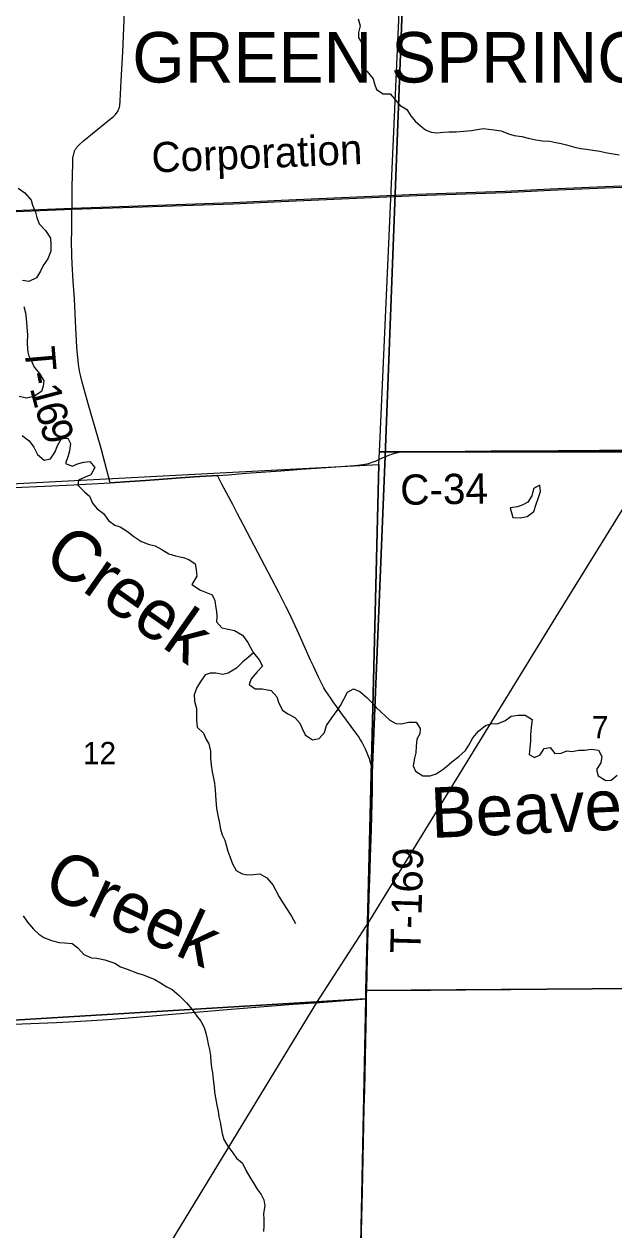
# Model space of a CAD drawing. Extents: x -8.5 to 18.7, y -20.3 to 7.
# Drawn here: x -2.162 to 0.051, y -15.571 to -11.043 of the extents above; entities that cross this region are included whole.
import ezdxf

# ---------------------------------------------------------------- set-up
doc = ezdxf.new("R2010")
doc.units = 0
for name, color, linetype in [('GM_X_Corporation', 7, 'Continuous'), ('GM_X_Corporation_Text', 7, 'Continuous'), ('GM_X_County_Road', 7, 'Continuous'), ('GM_X_County_Road_Text', 7, 'Continuous'), ('GM_X_Minor_Lake', 7, 'Continuous'), ('GM_X_Minor_River', 7, 'Continuous'), ('GM_X_Minor_River_Text', 7, 'Continuous'), ('GM_X_Rail_Line', 7, 'Continuous'), ('GM_X_Rail_Line_Text', 7, 'Continuous'), ('GM_X_Section', 7, 'Continuous'), ('GM_X_Section_Text', 7, 'Continuous'), ('GM_X_Township_Road', 7, 'Continuous'), ('GM_X_Township_Road_Text', 7, 'Continuous')]:
    doc.layers.add(name, color=color, linetype=linetype)

msp = doc.modelspace()

# ---------------------------------------------------------------- linework, layer by layer
at = {"layer": 'GM_X_Corporation'}
for points in [[(-0.7294, -10.6288), (-0.8073, -12.6653), (-0.8563, -13.8563), (-0.8562, -13.8576), (-0.8558, -13.8824), (-0.8563, -13.9234), (-0.8576, -13.9681), (-0.8606, -14.0687), (-0.8638, -14.1703), (-0.8653, -14.2148), (-0.8687, -14.3231), (-0.8738, -14.4921), (-0.8766, -14.6077), (-0.8781, -14.6701), (-0.8783, -14.6907), (-0.8786, -14.7019), (-0.8791, -14.7405), (-0.8831, -14.922), (-0.8855, -15.0451), (-0.8872, -15.1105), (-0.8888, -15.1767), (-0.8939, -15.428), (-0.8959, -15.526), (-0.9022, -15.7882)], [(-0.9022, -15.7882), (-0.8959, -15.526), (-0.8939, -15.428), (-0.8888, -15.1767), (-0.8872, -15.1105), (-0.8855, -15.0451), (-0.8831, -14.922), (-0.8791, -14.7405), (-0.8786, -14.7019), (-0.8783, -14.6907), (-0.8781, -14.6701), (-0.8766, -14.6077), (-0.8738, -14.4921), (-0.8687, -14.3231), (-0.8653, -14.2148), (-0.8638, -14.1703), (-0.8606, -14.0687), (-0.8576, -13.9681), (-0.8563, -13.9234), (-0.8558, -13.8824), (-0.8562, -13.8576), (-0.8563, -13.8563), (-0.8073, -12.6653), (-0.7294, -10.6288)]]:
    msp.add_lwpolyline(points, dxfattribs=at)
at = {"layer": 'GM_X_County_Road'}
for points in [[(-1.4372, -12.7375), (-1.3968, -12.7349), (-1.3286, -12.7295), (-1.1997, -12.7202), (-1.1228, -12.7142), (-0.974, -12.7037), (-0.9244, -12.7003), (-0.8997, -12.6979), (-0.8839, -12.6955), (-0.8694, -12.6922), (-0.8565, -12.6883), (-0.8438, -12.6835), (-0.8292, -12.6769), (-0.8068, -12.6664)], [(-0.8068, -12.6664), (-0.7961, -12.6621), (-0.7842, -12.6581), (-0.7707, -12.6535), (-0.7556, -12.6503), (-0.742, -12.6488), (-0.7319, -12.6483), (-0.7151, -12.6481), (-0.6765, -12.6472), (-0.5074, -12.6465), (-0.449, -12.6462), (-0.4092, -12.6457), (-0.3508, -12.6455), (-0.1581, -12.644), (-0.0848, -12.6435), (-0.0039, -12.6428), (0.0856, -12.6428)], [(-2.9024, -12.811), (-2.644, -12.8008), (-2.4067, -12.7911), (-2.198, -12.7824), (-1.9759, -12.7724), (-1.8397, -12.7655)], [(-1.8397, -12.7655), (-1.7654, -12.7603), (-1.7075, -12.7563), (-1.5256, -12.7433), (-1.4372, -12.7375)]]:
    msp.add_lwpolyline(points, dxfattribs=at)
at = {"layer": 'GM_X_Minor_Lake'}
for points in [[(-0.3384, -12.859), (-0.328, -12.8955), (-0.3016, -12.8971), (-0.2743, -12.8912), (-0.25, -12.8724), (-0.2415, -12.8459), (-0.2323, -12.8209), (-0.2246, -12.7975), (-0.2267, -12.7739), (-0.243, -12.783)], [(-0.243, -12.783), (-0.251, -12.7874), (-0.2572, -12.814), (-0.2717, -12.8382), (-0.2907, -12.8479), (-0.3112, -12.8554), (-0.3384, -12.859)]]:
    msp.add_lwpolyline(points, dxfattribs=at)
at = {"layer": 'GM_X_Minor_River'}
for points in [[(-0.9083, -11.0235), (-0.9009, -11.0493), (-0.9071, -11.0736), (-0.9073, -11.0933), (-0.893, -11.1184), (-0.8811, -11.1435), (-0.8866, -11.17), (-0.8936, -11.1988), (-0.8748, -11.2209), (-0.853, -11.2476), (-0.847, -11.2674), (-0.8404, -11.2879), (-0.8155, -11.3047), (-0.7882, -11.3049), (-0.7725, -11.3239), (-0.7522, -11.3468), (-0.7265, -11.3637), (-0.7115, -11.3873), (-0.695, -11.4071), (-0.6754, -11.4247), (-0.6558, -11.44), (-0.6354, -11.4484), (-0.6135, -11.4508), (-0.5885, -11.4487), (-0.5688, -11.4473), (-0.5416, -11.4467), (-0.5135, -11.4446), (-0.484, -11.4418), (-0.462, -11.4381), (-0.4393, -11.4352), (-0.4196, -11.4376), (-0.3984, -11.4393), (-0.3719, -11.4432), (-0.3448, -11.4548), (-0.3229, -11.461), (-0.2949, -11.4642), (-0.2707, -11.4712), (-0.2427, -11.4774), (-0.2177, -11.4806), (-0.1897, -11.4823), (-0.1671, -11.487), (-0.1466, -11.4909), (-0.127, -11.4963), (-0.1005, -11.5041), (-0.0741, -11.5096), (-0.0521, -11.5127), (-0.0279, -11.5159), (-0.0022, -11.5199), (0.019, -11.5246), (0.0409, -11.5292), (0.0711, -11.5332)], [(-2.1853, -11.6584), (-2.1597, -11.6768), (-2.1364, -11.7034), (-2.1312, -11.7224), (-2.1193, -11.7483), (-2.1148, -11.7688), (-2.1059, -11.7931), (-2.0818, -11.8175), (-2.0638, -11.8465), (-2.0617, -11.87), (-2.0626, -11.8958), (-2.0734, -11.9245), (-2.0909, -11.9495), (-2.1009, -11.9699), (-2.1154, -11.9956), (-2.1442, -12.0091), (-2.1684, -12.0052)], [(-2.1629, -12.103), (-2.157, -12.1274), (-2.1549, -12.1478), (-2.152, -12.1797), (-2.1499, -12.2108), (-2.1516, -12.2366), (-2.1495, -12.2654), (-2.1458, -12.2859), (-2.1339, -12.311), (-2.1242, -12.3308), (-2.1046, -12.3544), (-2.0881, -12.3826), (-2.0913, -12.4023), (-2.0974, -12.422), (-2.1255, -12.4408), (-2.1536, -12.4475), (-2.1808, -12.4413)], [(-2.1695, -12.5877), (-2.1432, -12.6076), (-2.1259, -12.632), (-2.1117, -12.6586), (-2.0868, -12.68), (-2.0633, -12.6748), (-2.0465, -12.6483), (-2.0373, -12.6249), (-2.022, -12.5992), (-1.9986, -12.597), (-1.9889, -12.6176), (-1.992, -12.6448), (-1.9975, -12.6645), (-2.0075, -12.6933), (-1.981, -12.7026), (-1.9621, -12.6943), (-1.9386, -12.6876), (-1.9158, -12.6847), (-1.8971, -12.7076), (-1.9116, -12.7348), (-1.9336, -12.7445), (-1.9579, -12.755), (-1.9603, -12.7747), (-1.9362, -12.7991), (-1.9166, -12.8152), (-1.9062, -12.8418), (-1.8889, -12.8624), (-1.8648, -12.8807), (-1.846, -12.9066), (-1.8219, -12.9242), (-1.8023, -12.9311), (-1.7751, -12.948), (-1.751, -12.9663), (-1.7246, -12.9847), (-1.6975, -12.9954), (-1.6703, -13.0024), (-1.6454, -13.0154), (-1.619, -13.0315), (-1.5948, -13.04), (-1.5661, -13.0455), (-1.5449, -13.0532), (-1.5208, -13.07), (-1.5164, -13.0913), (-1.5143, -13.1155), (-1.5326, -13.1465), (-1.501, -13.1687), (-1.4761, -13.178), (-1.4564, -13.1864), (-1.4467, -13.2077)], [(-1.4467, -13.2077), (-1.4438, -13.2267), (-1.4409, -13.2479), (-1.4395, -13.2669), (-1.4404, -13.2874), (-1.4208, -13.3103), (-1.3966, -13.3149), (-1.3732, -13.3204), (-1.343, -13.3372), (-1.3228, -13.3647), (-1.3123, -13.3837), (-1.3018, -13.4035), (-1.28, -13.4294), (-1.2673, -13.4537), (-1.2879, -13.4749), (-1.3099, -13.5013), (-1.3184, -13.5225), (-1.2958, -13.5393), (-1.2686, -13.5394), (-1.2353, -13.5449), (-1.2135, -13.5693), (-1.2068, -13.5921), (-1.1933, -13.6187), (-1.173, -13.6325), (-1.1466, -13.6471), (-1.1278, -13.6684), (-1.1196, -13.6874), (-1.1076, -13.711), (-1.0805, -13.7309), (-1.0555, -13.7257), (-1.0349, -13.7031), (-1.028, -13.6766), (-1.0074, -13.6479), (-0.9875, -13.6207), (-0.9746, -13.601), (-0.9631, -13.5783), (-0.9493, -13.5519), (-0.9258, -13.5391), (-0.9024, -13.5491), (-0.8768, -13.5712), (-0.8572, -13.5903), (-0.8414, -13.6094), (-0.7903, -13.6567), (-0.7676, -13.6689), (-0.748, -13.6698), (-0.7184, -13.6639), (-0.6912, -13.6641), (-0.6762, -13.6877), (-0.6778, -13.7081), (-0.6885, -13.7278), (-0.6917, -13.7536), (-0.6926, -13.7786), (-0.698, -13.7991), (-0.702, -13.8286), (-0.6938, -13.8484), (-0.6659, -13.8652), (-0.6386, -13.8654), (-0.6166, -13.8579), (-0.5863, -13.8376), (-0.5574, -13.8135), (-0.5315, -13.7932), (-0.5064, -13.7706), (-0.4942, -13.7502), (-0.4789, -13.7229), (-0.4568, -13.6973), (-0.431, -13.6762), (-0.4075, -13.6687), (-0.3878, -13.6704), (-0.359, -13.6591), (-0.3347, -13.6418), (-0.3089, -13.6382), (-0.2817, -13.6383), (-0.256, -13.6544), (-0.2592, -13.6832), (-0.2617, -13.7128), (-0.2618, -13.734), (-0.265, -13.7606), (-0.2674, -13.7856), (-0.247, -13.7963), (-0.2265, -13.7873), (-0.2113, -13.7624), (-0.1886, -13.7595), (-0.1705, -13.7816), (-0.1471, -13.7802), (-0.1258, -13.772), (-0.1062, -13.7744), (-0.0804, -13.7692), (-0.0592, -13.7686), (-0.035, -13.7649), (-0.007, -13.7689), (0.005, -13.7932), (0.0018, -13.8167), (-0.015, -13.8416), (-0.0083, -13.866), (0.0203, -13.8836), (0.0408, -13.8814), (0.0628, -13.8633)], [(-1.3012, -13.4041), (-1.3216, -13.4216), (-1.3414, -13.4374), (-1.3657, -13.4615), (-1.3968, -13.4803), (-1.4165, -13.4855), (-1.443, -13.48), (-1.4642, -13.4799), (-1.4831, -13.4859), (-1.4999, -13.5101), (-1.5137, -13.5335), (-1.5237, -13.5615), (-1.5231, -13.5858), (-1.5157, -13.6131), (-1.5158, -13.6359), (-1.5159, -13.6564), (-1.513, -13.6829), (-1.4897, -13.7051), (-1.48, -13.7264), (-1.4695, -13.7454), (-1.4629, -13.7735), (-1.463, -13.7978), (-1.4601, -13.8251), (-1.4565, -13.8509), (-1.4513, -13.8744), (-1.4477, -13.8934), (-1.4455, -13.9177), (-1.4441, -13.9367), (-1.4435, -13.9579), (-1.4407, -13.9875), (-1.4355, -14.0149), (-1.4311, -14.0376), (-1.4252, -14.0657), (-1.4193, -14.087), (-1.4096, -14.1075), (-1.4029, -14.1296), (-1.3977, -14.1486), (-1.391, -14.1691), (-1.3806, -14.1964), (-1.3671, -14.2208), (-1.3437, -14.2331), (-1.3226, -14.237), (-1.3014, -14.2356), (-1.2779, -14.2334), (-1.2522, -14.2488), (-1.2297, -14.2747), (-1.2185, -14.2937), (-1.205, -14.3203), (-1.1945, -14.3393), (-1.1585, -14.3927), (-1.1435, -14.42)], [(-2.1656, -14.3908), (-2.1499, -14.4151), (-2.1273, -14.4418), (-2.1078, -14.4601), (-2.0882, -14.4724), (-2.0595, -14.4839), (-2.0315, -14.4917), (-2.0103, -14.4933), (-1.9824, -14.495), (-1.9613, -14.5118), (-1.938, -14.5369), (-1.91, -14.5492), (-1.8896, -14.5509), (-1.8594, -14.5571), (-1.8224, -14.5694), (-1.8005, -14.5832), (-1.7763, -14.5917), (-1.7371, -14.6071), (-1.7159, -14.6133), (-1.6933, -14.6217), (-1.6714, -14.631), (-1.651, -14.6425), (-1.6269, -14.6578), (-1.6073, -14.6685), (-1.5809, -14.6899), (-1.5531, -14.7174), (-1.5313, -14.7433), (-1.514, -14.7676), (-1.4998, -14.7874), (-1.4863, -14.8103), (-1.4804, -14.8323), (-1.4752, -14.8528), (-1.4715, -14.8733), (-1.4671, -14.8931), (-1.4635, -14.9158), (-1.4613, -14.9394), (-1.4592, -14.9606), (-1.4555, -14.9804), (-1.4526, -15.0062), (-1.4498, -15.035), (-1.4484, -15.054)], [(-1.4484, -15.054), (-1.4439, -15.0745), (-1.4396, -15.1018), (-1.4337, -15.1254), (-1.4315, -15.1466), (-1.4271, -15.1656), (-1.4227, -15.1876), (-1.419, -15.2081), (-1.4131, -15.2309), (-1.3981, -15.256), (-1.3786, -15.2819), (-1.3651, -15.301), (-1.3425, -15.32), (-1.3298, -15.3489), (-1.3155, -15.3733), (-1.299, -15.3984), (-1.2878, -15.4182), (-1.2735, -15.4372), (-1.2631, -15.4578), (-1.2594, -15.4806), (-1.2641, -15.5086), (-1.2635, -15.5314), (-1.2629, -15.5556), (-1.2645, -15.5769)]]:
    msp.add_lwpolyline(points, dxfattribs=at)
at = {"layer": 'GM_X_Rail_Line'}
for points in [[(-4.5197, -20.262), (-4.302, -19.9023), (-3.8337, -19.1615), (-3.3722, -18.402), (-3.0035, -17.8228), (-2.5461, -17.0881), (-2.3673, -16.8107), (-1.6987, -15.76), (-1.0634, -14.7163), (-0.8647, -14.409), (-0.5398, -13.878), (-0.1554, -13.2519), (0.2117, -12.6573), (0.7735, -11.7893), (0.878, -11.6305)], [(-2.8573, -11.7692), (-1.9824, -11.7333), (-1.3786, -11.7124), (-1.1982, -11.7042), (-0.6892, -11.6812), (-0.3572, -11.6696), (-0.1879, -11.6614), (0.0172, -11.6524), (0.2408, -11.6442), (0.427, -11.6364), (0.5865, -11.6298), (0.8785, -11.6267), (1.3104, -11.6368), (1.8916, -11.6466), (2.137, -11.6505)], [(-2.8571, -11.7742), (-1.9822, -11.7382), (-1.3784, -11.7174), (-1.1979, -11.7091), (-0.689, -11.6862), (-0.357, -11.6746), (-0.1877, -11.6664), (0.0174, -11.6574), (0.241, -11.6491)]]:
    msp.add_lwpolyline(points, dxfattribs=at)
at = {"layer": 'GM_X_Section'}
for points in [[(-0.7383, -10.6339), (1.1828, -10.6703), (1.1777, -12.6489), (-0.8294, -12.6494)], [(-0.8294, -12.6494), (1.1777, -12.6489), (1.1578, -14.6567), (-0.8797, -14.6721), (-0.8312, -12.6964)], [(-2.9026, -12.8057), (-0.8312, -12.6964), (-0.8797, -14.6721), (-0.8807, -14.7032), (-2.8839, -14.825)], [(-0.8797, -14.6721), (1.1578, -14.6567), (1.1642, -16.6782), (-0.9213, -16.7479), (-0.9212, -16.7237), (-0.8807, -14.7032)], [(-2.8839, -14.825), (-0.8807, -14.7032), (-0.9212, -16.7237), (-2.8804, -16.8389)]]:
    msp.add_lwpolyline(points, close=True, dxfattribs=at)
at = {"layer": 'GM_X_Township_Road'}
for points in [[(-1.8397, -12.7655), (-1.8412, -12.76), (-1.8523, -12.7182), (-1.8739, -12.637), (-1.8958, -12.5592), (-1.919, -12.478), (-1.9446, -12.3871), (-1.9496, -12.3665), (-1.9528, -12.3508), (-1.9558, -12.336), (-1.9578, -12.3215), (-1.96, -12.3053), (-1.962, -12.284), (-1.964, -12.2557), (-1.9682, -12.185), (-1.974, -12.0745), (-1.9782, -12.0076), (-1.9818, -11.943), (-1.9835, -11.912), (-1.984, -11.8909), (-1.9842, -11.8787), (-1.9843, -11.8648), (-1.984, -11.8113), (-1.9832, -11.7577), (-1.9825, -11.7108), (-1.9817, -11.6648), (-1.9803, -11.599), (-1.9801, -11.5779), (-1.9798, -11.5542), (-1.9797, -11.5511), (-1.9794, -11.5472), (-1.9791, -11.544), (-1.9786, -11.5406), (-1.9775, -11.5346), (-1.9764, -11.5296), (-1.9752, -11.5257), (-1.9738, -11.5216), (-1.9728, -11.5191), (-1.9718, -11.5167), (-1.9709, -11.5148), (-1.9692, -11.5121), (-1.9676, -11.5095), (-1.9658, -11.5071), (-1.964, -11.5048), (-1.9598, -11.5), (-1.956, -11.4962), (-1.9394, -11.4811), (-1.9057, -11.4536), (-1.8441, -11.4033), (-1.8289, -11.3904), (-1.8201, -11.3817), (-1.8138, -11.374), (-1.8112, -11.3703), (-1.8093, -11.3666), (-1.8077, -11.3633), (-1.806, -11.3586), (-1.8046, -11.3544), (-1.8038, -11.3501), (-1.8014, -11.3304), (-1.7977, -11.2559), (-1.7926, -11.1466), (-1.7899, -11.0858), (-1.7844, -10.9703)], [(-1.4372, -12.7375), (-1.5256, -12.7433), (-1.7075, -12.7563), (-1.7654, -12.7603), (-1.8397, -12.7655)], [(-0.9736, -13.6276), (-0.989, -13.6064), (-0.9998, -13.591), (-1.0139, -13.5706), (-1.0184, -13.5645), (-1.0233, -13.5573), (-1.0297, -13.5476), (-1.0338, -13.5408), (-1.0376, -13.5347), (-1.0416, -13.5272), (-1.0454, -13.5196), (-1.0576, -13.4952), (-1.0771, -13.4534), (-1.0873, -13.4307), (-1.1308, -13.3345), (-1.1528, -13.2864), (-1.1604, -13.2696), (-1.1679, -13.2538), (-1.1804, -13.2292), (-1.2067, -13.1771), (-1.259, -13.0768), (-1.298, -13.0029), (-1.3394, -12.9246), (-1.3615, -12.8818), (-1.3795, -12.8471), (-1.4027, -12.8031), (-1.4203, -12.7699), (-1.4372, -12.7375)], [(-0.8588, -13.8329), (-0.8592, -13.8306), (-0.8602, -13.8255), (-0.8616, -13.8198), (-0.8638, -13.8112), (-0.8666, -13.8021), (-0.8699, -13.7925), (-0.8734, -13.7835), (-0.8772, -13.7747), (-0.8812, -13.7654), (-0.8851, -13.7577), (-0.8905, -13.7477), (-0.8957, -13.7381), (-0.9001, -13.7307), (-0.9068, -13.7196), (-0.9145, -13.709), (-0.9736, -13.6276)], [(-0.8558, -13.8574), (-0.8569, -13.8452), (-0.8581, -13.8375), (-0.8588, -13.8329)], [(-0.8776, -14.6712), (-0.8762, -14.6088), (-0.8733, -14.4932), (-0.8682, -14.3242), (-0.8649, -14.2159), (-0.8633, -14.1714), (-0.8602, -14.0698), (-0.8572, -13.9692), (-0.8558, -13.9245), (-0.8553, -13.8835), (-0.8557, -13.8587), (-0.8558, -13.8574)], [(-0.8776, -14.6712), (-0.85, -14.671), (-0.8202, -14.6708), (-0.7945, -14.6707), (-0.7685, -14.6706), (-0.7401, -14.6707), (-0.7267, -14.67), (-0.7143, -14.6704), (-0.697, -14.6701), (-0.6772, -14.6701), (-0.6498, -14.67), (-0.6374, -14.6699), (-0.584, -14.6694), (-0.5579, -14.6691), (-0.5219, -14.6688), (-0.5058, -14.6687), (-0.4834, -14.6684), (-0.4449, -14.668), (-0.389, -14.6679), (-0.3629, -14.6678), (-0.3368, -14.6678), (-0.2089, -14.6667), (-0.1156, -14.6659), (0.0485, -14.6641), (0.1221, -14.6635)], [(-2.8788, -14.8248), (-2.8416, -14.8233), (-2.7559, -14.8201), (-2.6242, -14.8145), (-2.403, -14.8057), (-2.3285, -14.8031), (-2.1061, -14.7942), (-2.0415, -14.7913), (-1.9707, -14.7876), (-1.9099, -14.784), (-1.8491, -14.7804), (-1.7859, -14.7754), (-1.6806, -14.7667), (-1.4006, -14.7435), (-1.2779, -14.7335), (-1.1527, -14.7236), (-1.0535, -14.7163), (-0.9419, -14.7084), (-0.8781, -14.703)], [(-0.9188, -16.7249), (-0.919, -16.7092), (-0.9189, -16.6644), (-0.9181, -16.6023), (-0.9163, -16.509), (-0.9126, -16.3487), (-0.9098, -16.2095), (-0.9065, -16.0529), (-0.9046, -15.9609), (-0.9028, -15.8751), (-0.9017, -15.7893), (-0.8955, -15.5271), (-0.8935, -15.4291), (-0.8884, -15.1778), (-0.8867, -15.1116), (-0.8851, -15.0462), (-0.8827, -14.9231), (-0.8787, -14.7416), (-0.8781, -14.703)], [(-0.8781, -14.703), (-0.8778, -14.6918), (-0.8776, -14.6712)]]:
    msp.add_lwpolyline(points, dxfattribs=at)

# ---------------------------------------------------------------- texts
at = {"layer": 'GM_X_Corporation_Text'}
msp.add_text('GREEN SPRINGS', height=0.189394, rotation=0, dxfattribs=at).set_placement((-1.7566, -11.262))
at = {"layer": 'GM_X_County_Road_Text'}
msp.add_text('C-34', height=0.11364, rotation=0.9318, dxfattribs=at).set_placement((-0.7503, -12.8483))
at = {"layer": 'GM_X_Minor_River_Text'}
for s, height, rotation, p in [('Creek', 0.1895, 324.8656, (-2.0991, -13.0636)), ('Beaver', 0.18948, 2.5961, (-0.633, -14.0993)), ('Creek', 0.18949, 335.1591, (-2.0995, -14.3052))]:
    msp.add_text(s, height=height, rotation=rotation, dxfattribs=at).set_placement(p)
at = {"layer": 'GM_X_Rail_Line_Text'}
msp.add_text('Corporation', height=0.113258, rotation=2.3463, dxfattribs=at).set_placement((-1.6822, -11.6004))
at = {"layer": 'GM_X_Section_Text'}
for s, height, p in [('7', 0.0837, (-0.0318, -13.7249)), ('12', 0.08371, (-1.9418, -13.822))]:
    msp.add_text(s, height=height, rotation=0, dxfattribs=at).set_placement(p)
at = {"layer": 'GM_X_Township_Road_Text'}
for s, height, rotation, p in [('T', 0.1136, 274.9217, (-2.1613, -12.2579)), ('-', 0.1136, 280.8259, (-2.1522, -12.3552)), ('1', 0.1136, 284.7701, (-2.1416, -12.4094)), ('6', 0.1136, 285.7298, (-2.1232, -12.479)), ('9', 0.1136, 285.8586, (-2.1041, -12.5467)), ('T-169', 0.11364, 88.3151, (-0.6755, -14.5335))]:
    msp.add_text(s, height=height, rotation=rotation, dxfattribs=at).set_placement(p)

doc.saveas('drawing.dxf')
